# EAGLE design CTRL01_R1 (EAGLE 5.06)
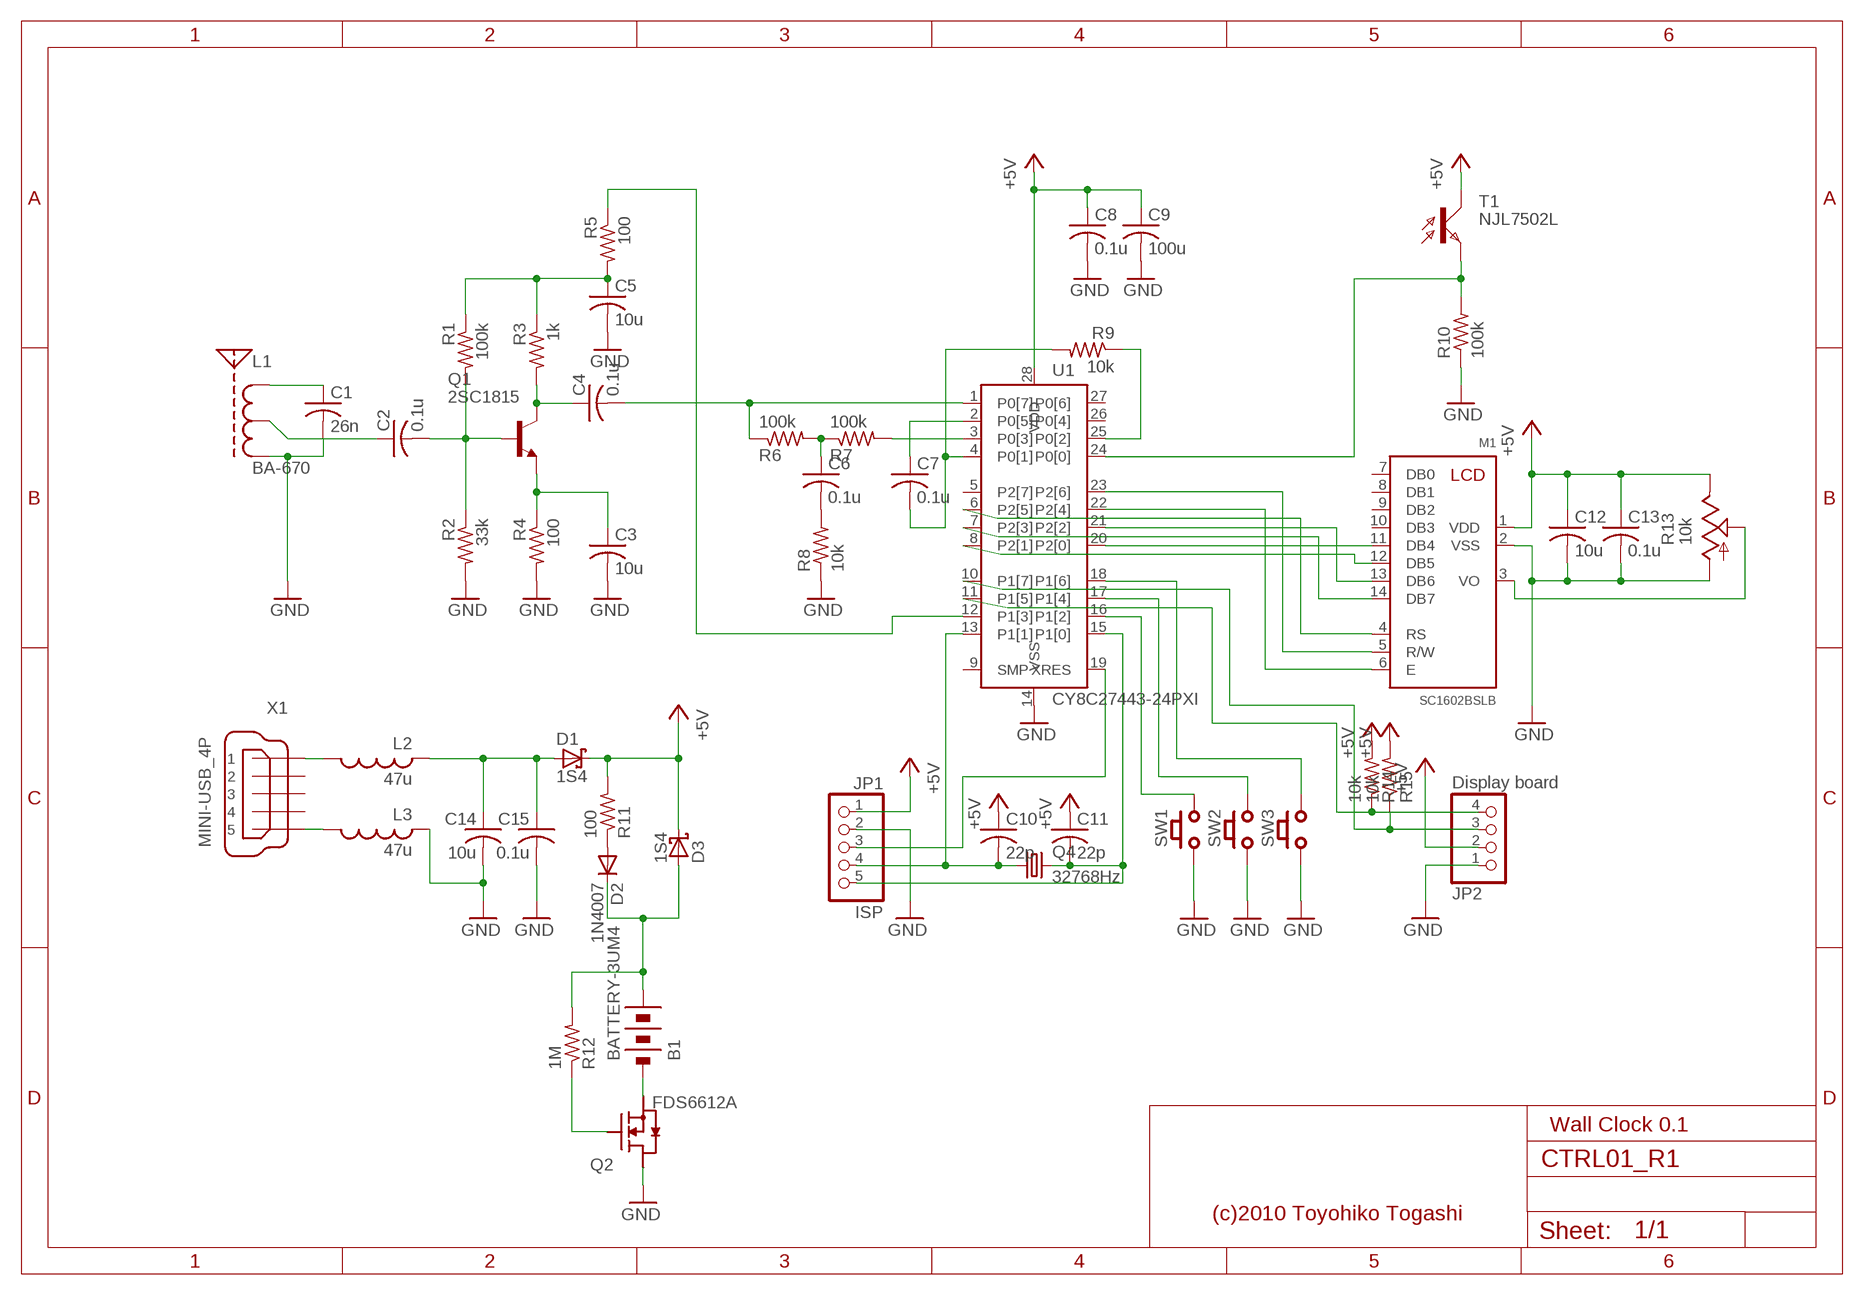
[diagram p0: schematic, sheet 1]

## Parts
B1  BATTERY-3UM4  [BATHLDR-UM4X3]
C1  26n  C-US025-024X044  [C025-024X044]
C2  0.1u  C-US025-024X044  [C025-024X044]
C3  10u  C-US025-024X044  [C025-024X044]
C4  0.1u  C-US050-025X075  [C050-025X075]
C5  10u  C-US025-024X044  [C025-024X044]
C6  0.1u  C-US025-024X044  [C025-024X044]
C7  0.1u  C-US025-024X044  [C025-024X044]
C8  0.1u  C-US025-024X044  [C025-024X044]
C9  100u  C-US025-024X044  [C025-024X044]
C10  22p  C-US025-024X044  [C025-024X044]
C11  22p  C-US025-024X044  [C025-024X044]
C12  10u  C-US025-024X044  [C025-024X044]
C13  0.1u  C-US025-024X044  [C025-024X044]
C14  10u  C-US025-024X044  [C025-024X044]
C15  0.1u  C-US025-024X044  [C025-024X044]
D1  1S4  SCHOTTKY-DIODEDO35-7  [DO35-7]
D2  1N4007  1N4148DO35-7  [DO35-7]
D3  1S4  SCHOTTKY-DIODEDO35-7  [DO35-7]
JP1  ISP  PINHD-1X5  [1X05]
JP2  Display board  PINHD-1X4  [1X04]
L1  BA-670  [BA-670]
L2  47u  L-US0204/5  [0204/5]
L3  47u  L-US0204/5  [0204/5]
M1  SC1602BSLB  [SC1602B]
Q1  2SC1815  [TO92-ECB]
Q2  FDS6612A  [SOP8]
Q4  32768Hz  CRYSTALTC26H  [TC26H]
R1  100k  R-US_0204/5  [0204/5]
R2  33k  R-US_0204/5  [0204/5]
R3  1k  R-US_0204/5  [0204/5]
R4  100  R-US_0204/5  [0204/5]
R5  100  R-US_0204/5  [0204/5]
R6  100k  R-US_0204/5  [0204/5]
R7  100k  R-US_0204/5  [0204/5]
R8  10k  R-US_0204/5  [0204/5]
R9  10k  R-US_0204/5  [0204/5]
R10  100k  R-US_0204/5  [0204/5]
R11  100  R-US_0204/5  [0204/5]
R12  1M  R-US_0204/5  [0204/5]
R13  10k  TRIM_US-B25P  [B25P]
R14  10k  R-US_0204/5  [0204/5]
R15  10k  R-US_0204/5  [0204/5]
SW1  SWITCH-PUSH"  [SWITCH-PUSH]
SW2  SWITCH-PUSH"  [SWITCH-PUSH]
SW3  SWITCH-PUSH"  [SWITCH-PUSH]
T1  NJL7502L  LPT80A  [LPT80A]
U1  CY8C27443-24PXI  [DIL28-3]
X1  MINI-USB_4P  AKI-USB-MINI-B  [AKI-USB-MINI-B]

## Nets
+5V: C8.1 C9.1 C10.1 C11.1 C12.1 C13.1 D1.C D3.C JP1.1 JP2.2 M1.1(VDD) R11.2 R13.E R14.2 R15.2 T1.C U1.28(VDD)
N$1: C1.1 L1.NATURAL
N$2: C2.2 Q1.B R1.2 R2.1
N$3: C2.1 L1.BLACK
N$4: R7.2 U1.3(P0[3])
N$5: C3.1 Q1.E R4.1
N$6: C4.1 Q1.C R3.2
N$7: C7.1 U1.2(P0[5])
N$8: JP2.3 R15.1 U1.10(P1[7])
N$9: C6.1 R6.2 R7.1
N$10: C6.2 R8.2
N$11: C7.2 R9.2 U1.4(P0[1])
N$12: R9.1 U1.25(P0[2])
N$13: C4.2 R6.1 U1.1(P0[7])
N$14: JP2.4 R14.1 U1.11(P1[5])
N$16: R5.1 U1.12(P1[3])
N$17: M1.11(DB4) U1.20(P2[0])
N$18: M1.12(DB5) U1.8(P2[1])
N$19: M1.13(DB6) U1.21(P2[2])
N$20: M1.14(DB7) U1.7(P2[3])
N$21: M1.6(E) U1.22(P2[4])
N$22: M1.5(R/W) U1.23(P2[6])
N$23: M1.4(RS) U1.6(P2[5])
N$24: B1.P$2(MINUS) Q2.P$1(S)
N$25: D2.A R11.1
N$26: C5.1 R1.1 R3.1 R5.2
N$27: Q2.P$4(G) R12.1
N$28: B1.P$1(PLUS) D2.C D3.A R12.2
N$30: M1.3(VO) R13.S
N$31: C10.2 JP1.4 Q4.1 U1.13(P1[1])
N$32: C11.2 JP1.5 Q4.2 U1.15(P1[0])
N$33: SW1.P$2(A2) U1.16(P1[2])
N$34: JP1.3 U1.19(XRES)
N$35: SW2.P$2(A2) U1.17(P1[4])
N$36: SW3.P$2(A2) U1.18(P1[6])
N$37: R10.2 T1.E U1.24(P0[0])
N$38: L3.1 X1.5
N$39: C1.2 C3.2 C5.2 C8.2 C9.2 C12.2 C13.2 C14.2 C15.2 JP1.2 JP2.1 L1.GREEN L3.2 M1.2(VSS) Q2.P$5(D) R2.2 R4.2 R8.1 R10.1 R13.A SW1.P$1(A1) SW2.P$1(A1) SW3.P$1(A1) U1.14(VSS) ; supply symbol labelled GND
N$40: L2.1 X1.1
N$41: C14.1 C15.1 D1.A L2.2
Unconnected: M1.7(DB0) M1.8(DB1) M1.9(DB2) M1.10(DB3) U1.5(P2[7]) U1.26(P0[4]) U1.27(P0[6]) X1.2 X1.3 X1.4

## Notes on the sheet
- Wall Clock 0.1
- (c)2010 Toyohiko Togashi

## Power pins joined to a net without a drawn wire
SMP: U1.9(SMP)

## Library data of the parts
B1 = TOG:BATTERY-3: Battery 3cell
C1-C15 = rcl:C-US: CAPACITOR, American symbol
D1 D3 = diode:SCHOTTKY-DIODE: Schottky Diode
D2 = diode:1N4148: DIODE
JP1 = pinhead:PINHD-1X5: PIN HEADER
JP2 = pinhead:PINHD-1X4: PIN HEADER
L1 = TOG:BA-670: AIKO DENSHI MW band AM radio bar antenna 670uH +/-5% Q200~/790kHz 3x8x45mm
L2 L3 = rcl:L-US: INDUCTOR, American symbol
M1 = TOG:SC1602BSLB: Character LCD module
Q1 = transistor:2SC1815: NPN EPITAXIAL TRANSISTOR Source: TOSHIBA .. 2SC1815 1.pdf
Q2 = TOG:FDS6612A: N-ch MOS FET
Q4 = crystal:CRYSTAL: CRYSTAL
R1-R12 R14 R15 = rcl:R-US_: RESISTOR, American symbol
R13 = pot:TRIM_US-: POTENTIOMETER
SW1-SW3 = TOG:SWITCH-PUSH
T1 = opto-trans-siemens:LPT80A: PHOTO TRANSISTOR
U1 = TOG:CY8C27443: Cypress PSoC Mixe-Signal Array Flash16K,RAM256B, Digital block 8, Analog block 12
X1 = TOG:AKI-USB-MINI-B: Akizuki USB connector MINI-B type

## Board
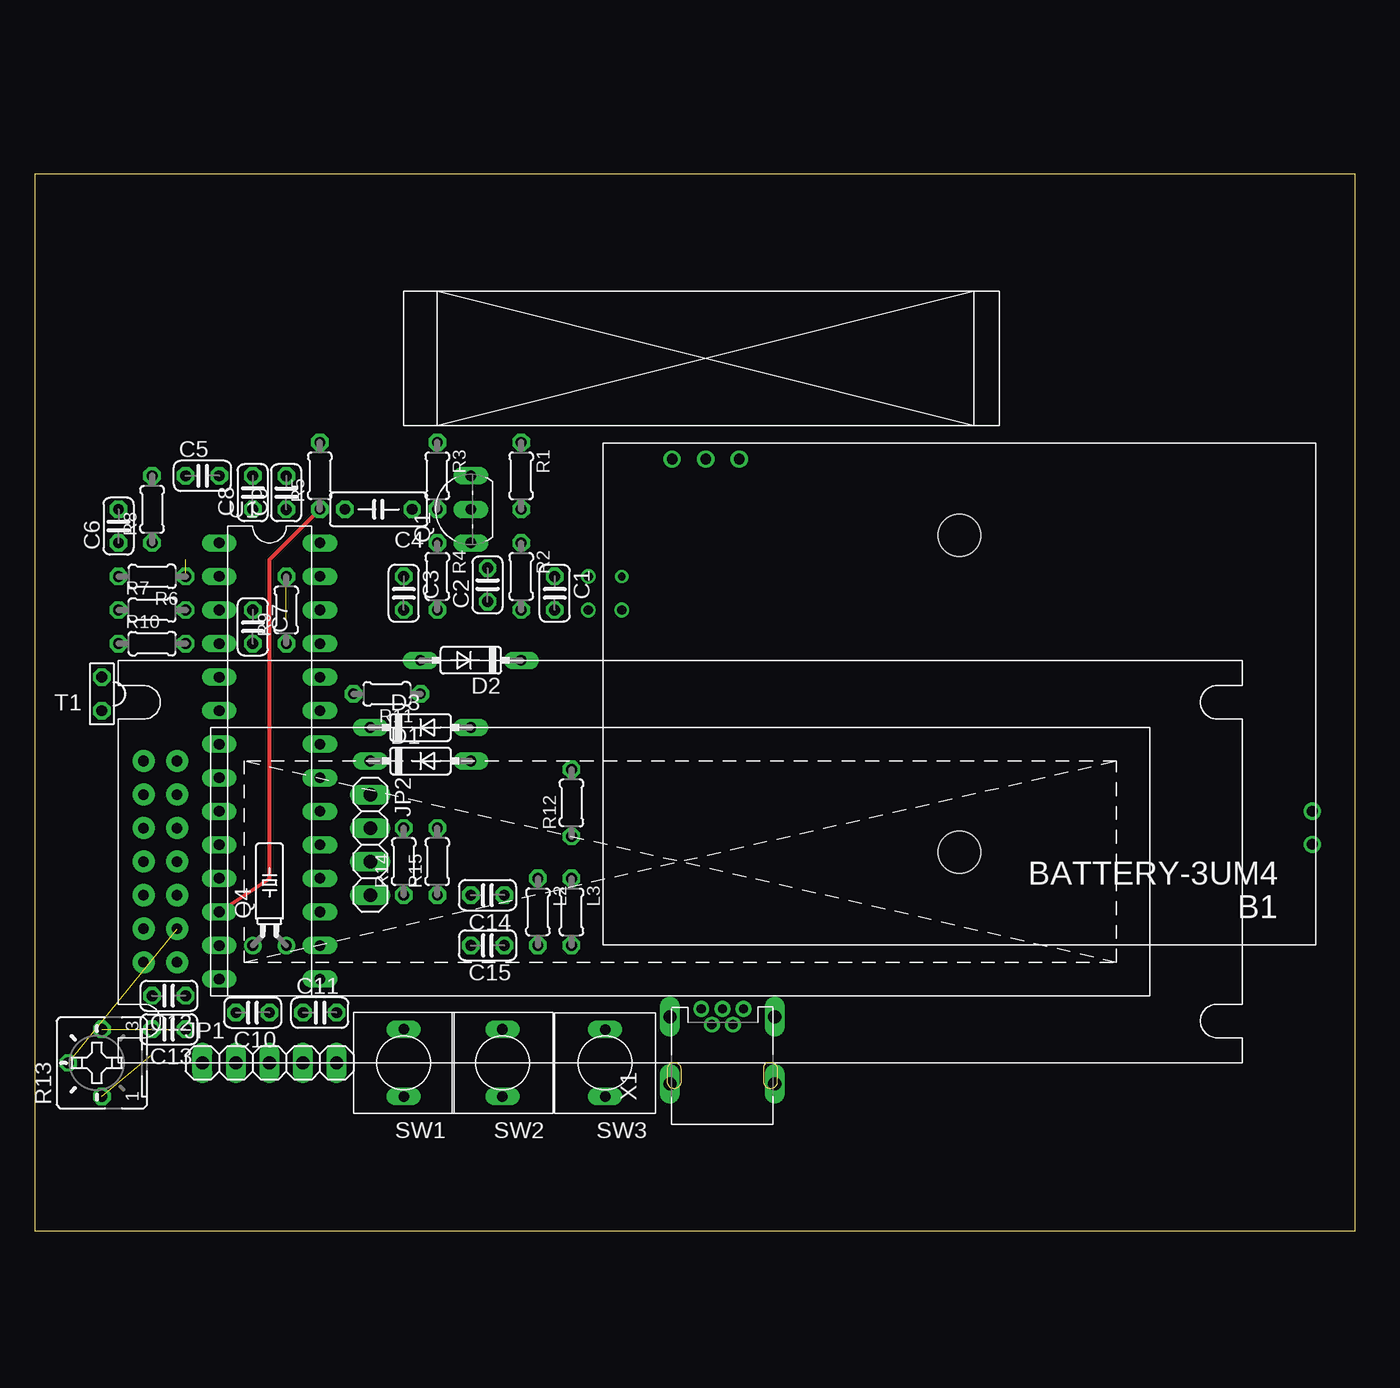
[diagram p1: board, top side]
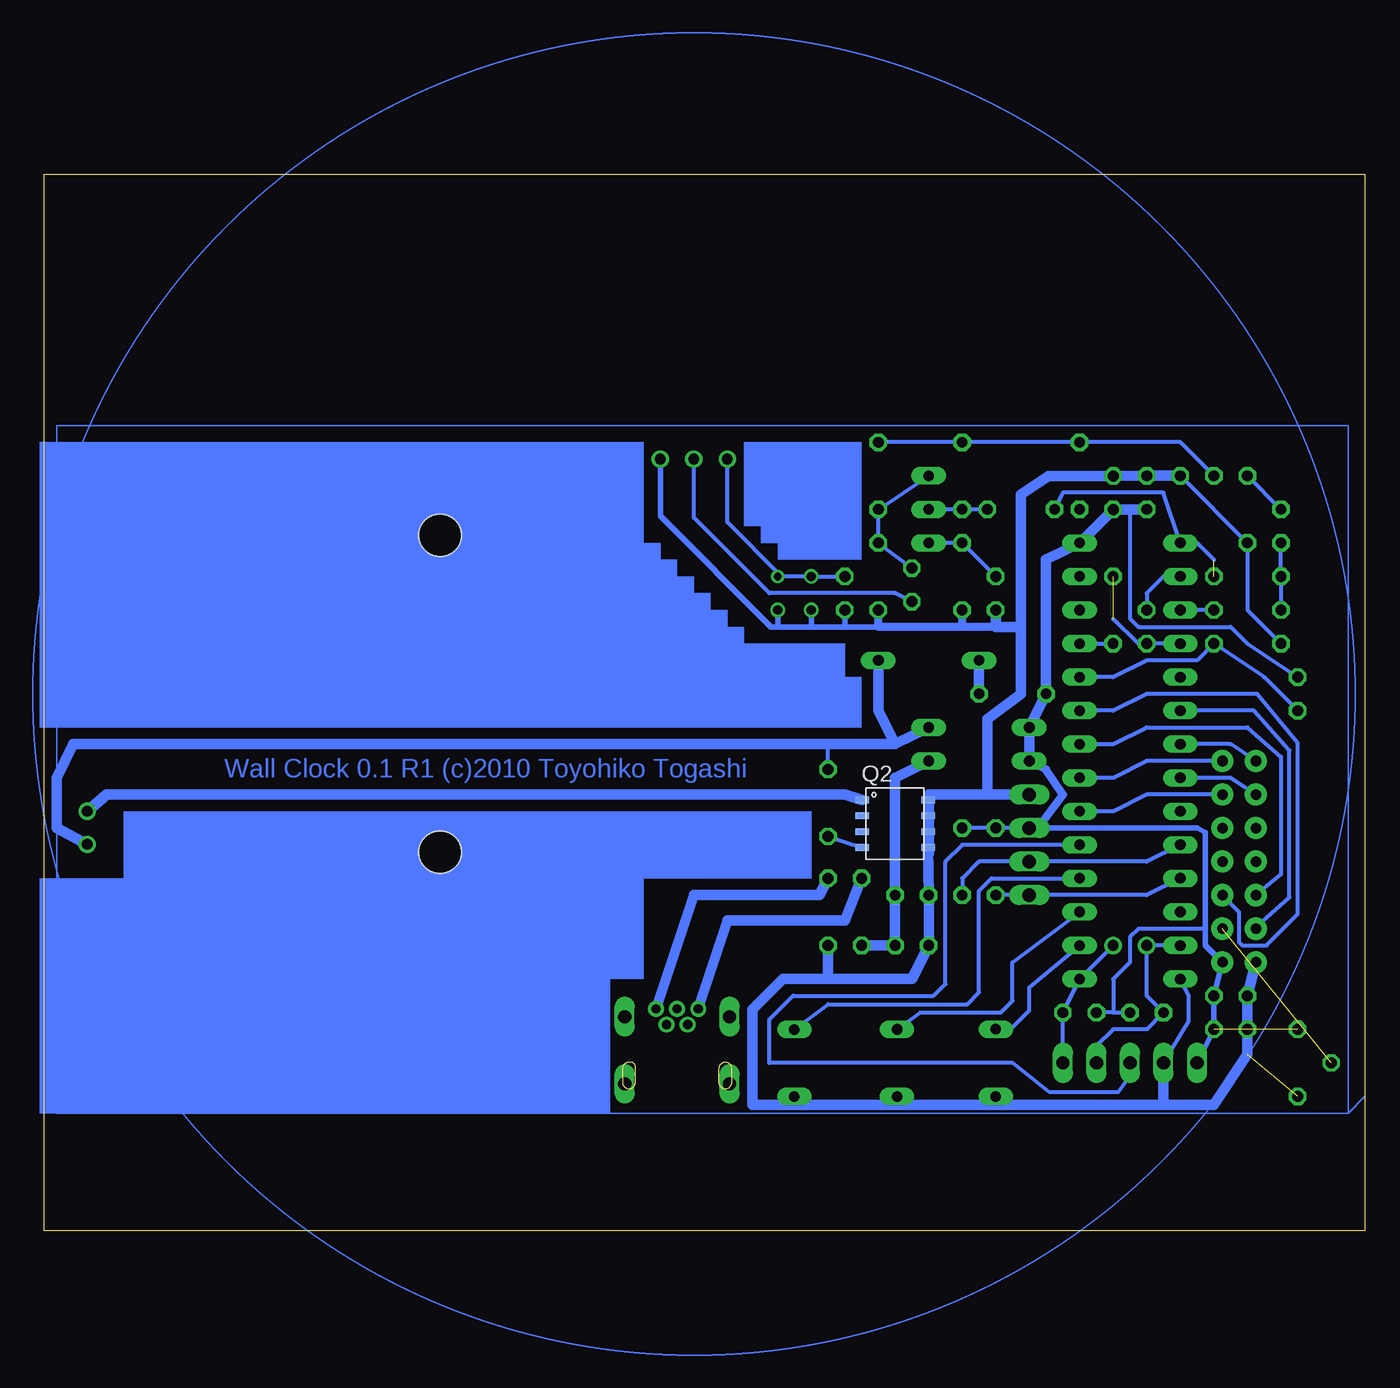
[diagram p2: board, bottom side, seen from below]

Size 100 x 80 mm. Coordinates in mm from the lower left corner, seen from the top.
Outline: 0,0 100,0 100,80 0,80 0,0
Copper layers (1*16): Top 0.035mm / dielectric 1.5mm / Bottom 0.035mm
Design rules "default": minimum track width 10mil, minimum drill 24mil, track to track 8mil, track to pad 8mil, pad to pad 8mil, via to via 8mil, smd to smd 8mil, copper to edge 40mil, drill to drill 8mil, minimum pad ring 10mil, minimum via ring 8mil, stop-mask expansion 4mil, vias tented up to drill 0mil, thermal gap 10mil

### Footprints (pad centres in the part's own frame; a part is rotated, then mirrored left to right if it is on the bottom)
BATHLDR-UM4X3 = drill 0.8 round: P$1 -26.714,11.396; P$2 -26.714,8.888 | hole 3.2: 0,-12; 0,12
C025-024X044 = drill 0.813 octagon: 1 -1.27,0; 2 1.27,0
C050-025X075 = drill 0.813 octagon: 1 -2.54,0; 2 2.54,0
DO35-7 = drill 0.813 long: A 3.81,0; C -3.81,0
1X05 = drill 1.016 long: 1 -5.08,0; 2 -2.54,0; 3 0,0; 4 2.54,0; 5 5.08,0
1X04 = drill 1.016 long: 1 -3.81,0; 2 -1.27,0; 3 1.27,0; 4 3.81,0
BA-670 = drill 0.8 round: BLACK 22.86,-2.54; GREEN 25.4,-2.54; NATURAL 20.32,-2.54
0204/5 = drill 0.813 octagon: 1 -2.54,0; 2 2.54,0
SC1602B = drill 0.8 pad 1.676 round: 1 5.08,5.08; 2 2.54,5.08; 3 5.08,7.62; 4 2.54,7.62; 5 5.08,10.16; 6 2.54,10.16; 7 5.08,12.7; 8 2.54,12.7; 9 5.08,15.24; 10 2.54,15.24; 11 5.08,17.78; 12 2.54,17.78; 13 5.08,20.32; 14 2.54,20.32
TO92-ECB = drill 0.813 long: B 2.54,0; C 0,0; E -2.54,0
SOP8 = smd 0.508 x 1.016: P$1 -1.8,-2.5; P$2 -0.6,-2.5; P$3 0.6,-2.5; P$4 1.8,-2.5; P$5 1.8,2.5; P$6 0.6,2.5; P$7 -0.6,2.5; P$8 -1.8,2.5
TC26H = drill 0.813 round: 1 -1.27,0; 2 1.27,0
B25P = drill 0.813 octagon: A -2.54,0; E 2.54,0; S 0,2.54
SWITCH-PUSH = drill 0.8 long: P$1 0,2.54; P$2 0,-2.54
LPT80A = drill 0.813 octagon: C 0,-1.27; E 0,1.27
DIL28-3 = drill 0.8 long: 1 -16.51,-3.81; 2 -13.97,-3.81; 3 -11.43,-3.81; 4 -8.89,-3.81; 5 -6.35,-3.81; 6 -3.81,-3.81; 7 -1.27,-3.81; 8 1.27,-3.81; 9 3.81,-3.81; 10 6.35,-3.81; 11 8.89,-3.81; 12 11.43,-3.81; 13 13.97,-3.81; 14 16.51,-3.81; 15 16.51,3.81; 16 13.97,3.81; 17 11.43,3.81; 18 8.89,3.81; 19 6.35,3.81; 20 3.81,3.81; 21 1.27,3.81; 22 -1.27,3.81; 23 -3.81,3.81; 24 -6.35,3.81; 25 -8.89,3.81; 26 -11.43,3.81; 27 -13.97,3.81; 28 -16.51,3.81
AKI-USB-MINI-B = drill 0.7 pad 1.016 round: 1 2.825,1.6; 2 1.625,0.8; 3 2.825,0; 4 1.625,-0.8; 5 2.825,-1.6 | drill 1 pad 1.422 long: M1 -2.86,3.967; M2 -2.86,-3.967; M3 2.22,3.967; M4 2.22,-3.967

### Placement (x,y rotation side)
B1  70.02,40.64 180 top
C1  39.37,48.26 270 top
C2  34.29,48.9 90 top
C3  27.94,48.26 270 top
C4  26.04,54.61 180 top
C5  12.7,57.15 0 top
C6  6.35,53.34 90 top
C7  16.51,45.72 270 top
C8  16.51,55.88 90 top
C9  19.05,55.87 90 top
C10  16.51,16.51 180 top
C11  21.59,16.51 0 top
C12  10.16,17.78 180 top
C13  10.16,15.24 180 top
C14  34.29,25.4 180 top
C15  34.29,21.59 180 top
D1  29.21,35.56 0 top
D2  33.02,43.18 180 top
D3  29.21,38.1 0 top
JP1  17.78,12.7 0 top
JP2  25.4,29.21 270 top
L1  27.94,60.96 0 top
L2  38.1,24.13 270 top
L3  40.64,24.13 270 top
M1  5.71,15.24 0 top
Q1  33.02,54.61 90 top
Q2  35.56,30.81 270 bottom
Q4  17.78,21.59 0 top
R1  36.83,57.15 270 top
R2  36.83,49.53 270 top
R3  30.48,57.15 270 top
R4  30.48,49.53 270 top
R5  21.59,57.15 90 top
R6  8.89,49.53 180 top
R7  8.89,46.99 0 top
R8  8.89,54.61 90 top
R9  19.05,46.99 90 top
R10  8.89,44.45 0 top
R11  26.67,40.64 180 top
R12  40.64,32.38 90 top
R13  5.08,12.7 90 top
R14  27.94,27.94 90 top
R15  30.48,27.94 90 top
SW1  27.94,12.7 180 top
SW2  35.42,12.7 180 top
SW3  43.19,12.69 180 top
T1  5.08,40.64 180 top
U1  17.78,35.56 270 top
X1  52.07,13.97 90 top

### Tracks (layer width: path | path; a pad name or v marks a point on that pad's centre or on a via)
+5V  (1 unrouted)
  Bottom 0.305: T1.C 8.89,44.45 10.16,45.72 17.14,45.72 17.78,46.35 17.78,54.6 | 19.05,16.51 C10.1 | 19.05,16.51 19.05,19.05 17.78,20.32 17.78,22.23 17.14,22.86 12.06,22.86 | 19.05,16.51 C11.1 | R15.2 R14.2 JP2.2
  Bottom 0.406: JP1.1 C13.1 C12.1 M1.1 12.06,21.59 12.06,22.86 12.06,30.16 12.7,30.48 24.77,30.48 JP2.2
  Bottom 0.61: D1.C 24.13,34.92 22.86,33.02 24.77,30.48
  Bottom 0.813: C8.1 17.78,54.6 C9.1 U1.28 24.13,50.8 R11.2 D3.C D1.C
N$1  (via drill 0.7)
  Bottom 0.305: L1.NATURAL 48.26,53.64 44.15,49.53 v41.91,49.53 C1.1
N$2
  Bottom 0.305: C2.2 R2.1 R1.2 Q1.B
N$3
  Bottom 0.305: C2.1 35.56,48.26 45.09,48.26 50.8,53.98 L1.BLACK
N$4
  Bottom 0.305: R7.2 U1.3
N$5
  Bottom 0.305: Q1.E R4.1 C3.1
N$6
  Bottom 0.305: Q1.C R3.2 C4.1
N$7
  Bottom 0.305: U1.2 15.24,49.53 16.51,48.26 C7.1
N$8
  Bottom 0.305: U1.10 16.51,27.94 JP2.3 29.21,27.94 30.48,26.67 R15.1
N$9
  Bottom 0.305: C6.1 R6.2 R7.1
N$10
  Bottom 0.305: R8.2 C6.2
N$11  (1 unrouted)
  Bottom 0.305: U1.4 C7.2 17.14,44.45 19.05,46.3
N$12
  Bottom 0.305: U1.25 R9.1
N$13  (1 unrouted)
  Bottom 0.305: C4.2 22.86,55.88 15.24,55.88 U1.1 12.7,52.07 11.43,50.8
N$14
  Bottom 0.305: U1.11 16.51,25.4 JP2.4 R14.1
N$15  (via drill 0.6)
  other vias: 44.45,49.53
N$16
  Top 0.305: U1.12 17.78,26.67 17.78,50.8 R5.1
N$17
  Bottom 0.305: M1.11 16.51,33.02 19.05,31.75 U1.20
N$18
  Bottom 0.305: M1.12 10.16,34.29 U1.8
N$19
  Bottom 0.305: M1.13 16.51,35.56 19.05,34.29 U1.21
N$20
  Bottom 0.305: M1.14 10.16,36.83 U1.7
N$21
  Bottom 0.305: U1.22 19.05,36.83 16.51,38.1 8.89,38.1 6.35,35.88 6.35,26.99 M1.6
N$22
  Bottom 0.305: M1.5 9.53,24.13 9.53,21.85 9.26,21.59 7.45,21.59 5.08,23.96 5.08,36.94 8.15,40.64 16.51,40.64 19.05,39.37 U1.23
N$23
  Bottom 0.305: M1.4 8.4,22.86 5.71,25.23 5.71,36.36 8.4,39.37 U1.6
N$24
  Bottom 0.813: Q2.P$1 39.37,33.02 95.25,33.02 B1.P$2
N$25
  Bottom 0.813: R11.1 D2.A
N$26
  Bottom 0.305: C5.1 13.97,59.69 R5.2 R3.1 R1.1
N$27
  Bottom 0.305: R12.1 Q2.P$4
N$28
  Bottom 0.305: R12.2 40.64,36.83
  Bottom 0.813: 35.56,36.83 D3.A | 35.56,36.83 40.64,36.83 97.79,36.83 99.06,34.29 99.06,30.48 B1.P$1 | D2.C 36.83,39.37 35.56,36.83
N$29
  Bottom 0.127: 1.27,8.89 0,10.16 | 1.27,8.89 99.06,8.89 99.06,60.96 1.27,60.96 1.27,8.89
N$30  (1 unrouted)
N$31
  Bottom 0.305: U1.13 Q4.1 16.51,17.78 C10.2 16.51,15.24 19.05,15.24 20.32,13.97 JP1.4
N$32
  Bottom 0.305: Q4.2 U1.15 C11.2 JP1.5
N$33
  Bottom 0.305: SW1.P$2 26.82,15.24 25.4,16.66 25.4,18.41 U1.16
N$34
  Bottom 0.305: JP1.3 17.78,11.69 18.68,10.48 23.87,10.48 26.67,12.7 45.09,12.7 45.09,15.98 43.29,17.78 32.65,17.78 31.75,18.68 31.75,27.94 30.48,29.21 U1.19
N$35
  Bottom 0.305: SW2.P$2 33.66,16.51 27.57,16.51 26.67,17.41 26.67,20.32 U1.17
N$36
  Bottom 0.305: SW3.P$2 40.64,17.14 30.11,17.14 29.21,18.04 29.21,25.72 28.26,26.67 U1.18
N$37
  Bottom 0.305: U1.24 19.05,41.91 16.51,43.18 12.7,43.18 R10.2 7.62,41.91 T1.E
N$38
  Bottom 0.813: X1.5 50.8,25.4 41.27,25.4 L3.1
N$39  (via drill 0.7)  (1 unrouted)
  Bottom 0.305: C5.2 R8.1 8.89,46.99 R10.1 | JP1.2 13.34,15.88 13.34,17.78 U1.14
  Bottom 0.406: 36.83,45.72 39.37,45.72 | 39.37,45.72 41.91,45.72 | 41.91,45.72 44.45,45.72 | 44.45,45.72 44.95,45.72 53.34,54.11 L1.GREEN | 39.37,45.72 C1.2 | 41.91,45.72 v41.91,46.99 | 44.45,45.72 v44.45,46.99
  Bottom 0.61: 30.48,45.72 36.83,45.72 R2.2 | 30.48,45.72 R4.2 | 27.94,45.72 30.48,45.72
  Bottom 0.813: 15.24,9.53 11.43,9.53 8.89,13.34 C13.2 C12.2 M1.2 | 15.24,9.53 JP1.2 | 28.57,33.02 JP2.1 | C5.2 C8.2 C9.2 23.98,57.15 26.04,55.73 26.04,45.72 | 28.57,33.02 28.57,38.73 26.04,40.64 26.04,45.72 | 26.04,45.72 27.94,45.72 C3.2 | 28.57,33.02 33.02,33.02 33.02,28.57 Q2.P$5 C14.2 C15.2 34.29,19.05 40.64,19.05 | 15.24,9.53 27.94,9.53 | 27.94,9.53 35.56,9.53 | 35.56,9.53 43.18,9.53 | 43.18,9.53 46.35,9.53 46.35,16.76 44.07,19.05 40.64,19.05 | 27.94,9.53 SW1.P$1 | 35.56,9.53 SW2.P$1 | 43.18,9.53 SW3.P$1 | 40.64,19.05 L3.2
N$40
  Bottom 0.813: X1.1 48.26,23.5 39.37,23.5 L2.1
N$41
  Bottom 0.813: D1.A 35.56,34.29 C14.1 C15.1 L2.2
(copper drawn outside any net)
  shapes: Bottom area x15, Bottom circle x1

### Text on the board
Bottom: Wall Clock 0.1 R1 (c)2010 Toyohiko Togashi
